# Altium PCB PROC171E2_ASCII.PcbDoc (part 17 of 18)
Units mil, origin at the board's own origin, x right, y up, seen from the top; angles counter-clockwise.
Board outline 7700 x 2300 mil, 6 copper layers (Top Layer, GND 1, SIG 1, SIG 2, GND 2, Bottom Layer), stack 61.062 mil thick; 938 components, 688 nets, 11933 pads, 1723 vias.
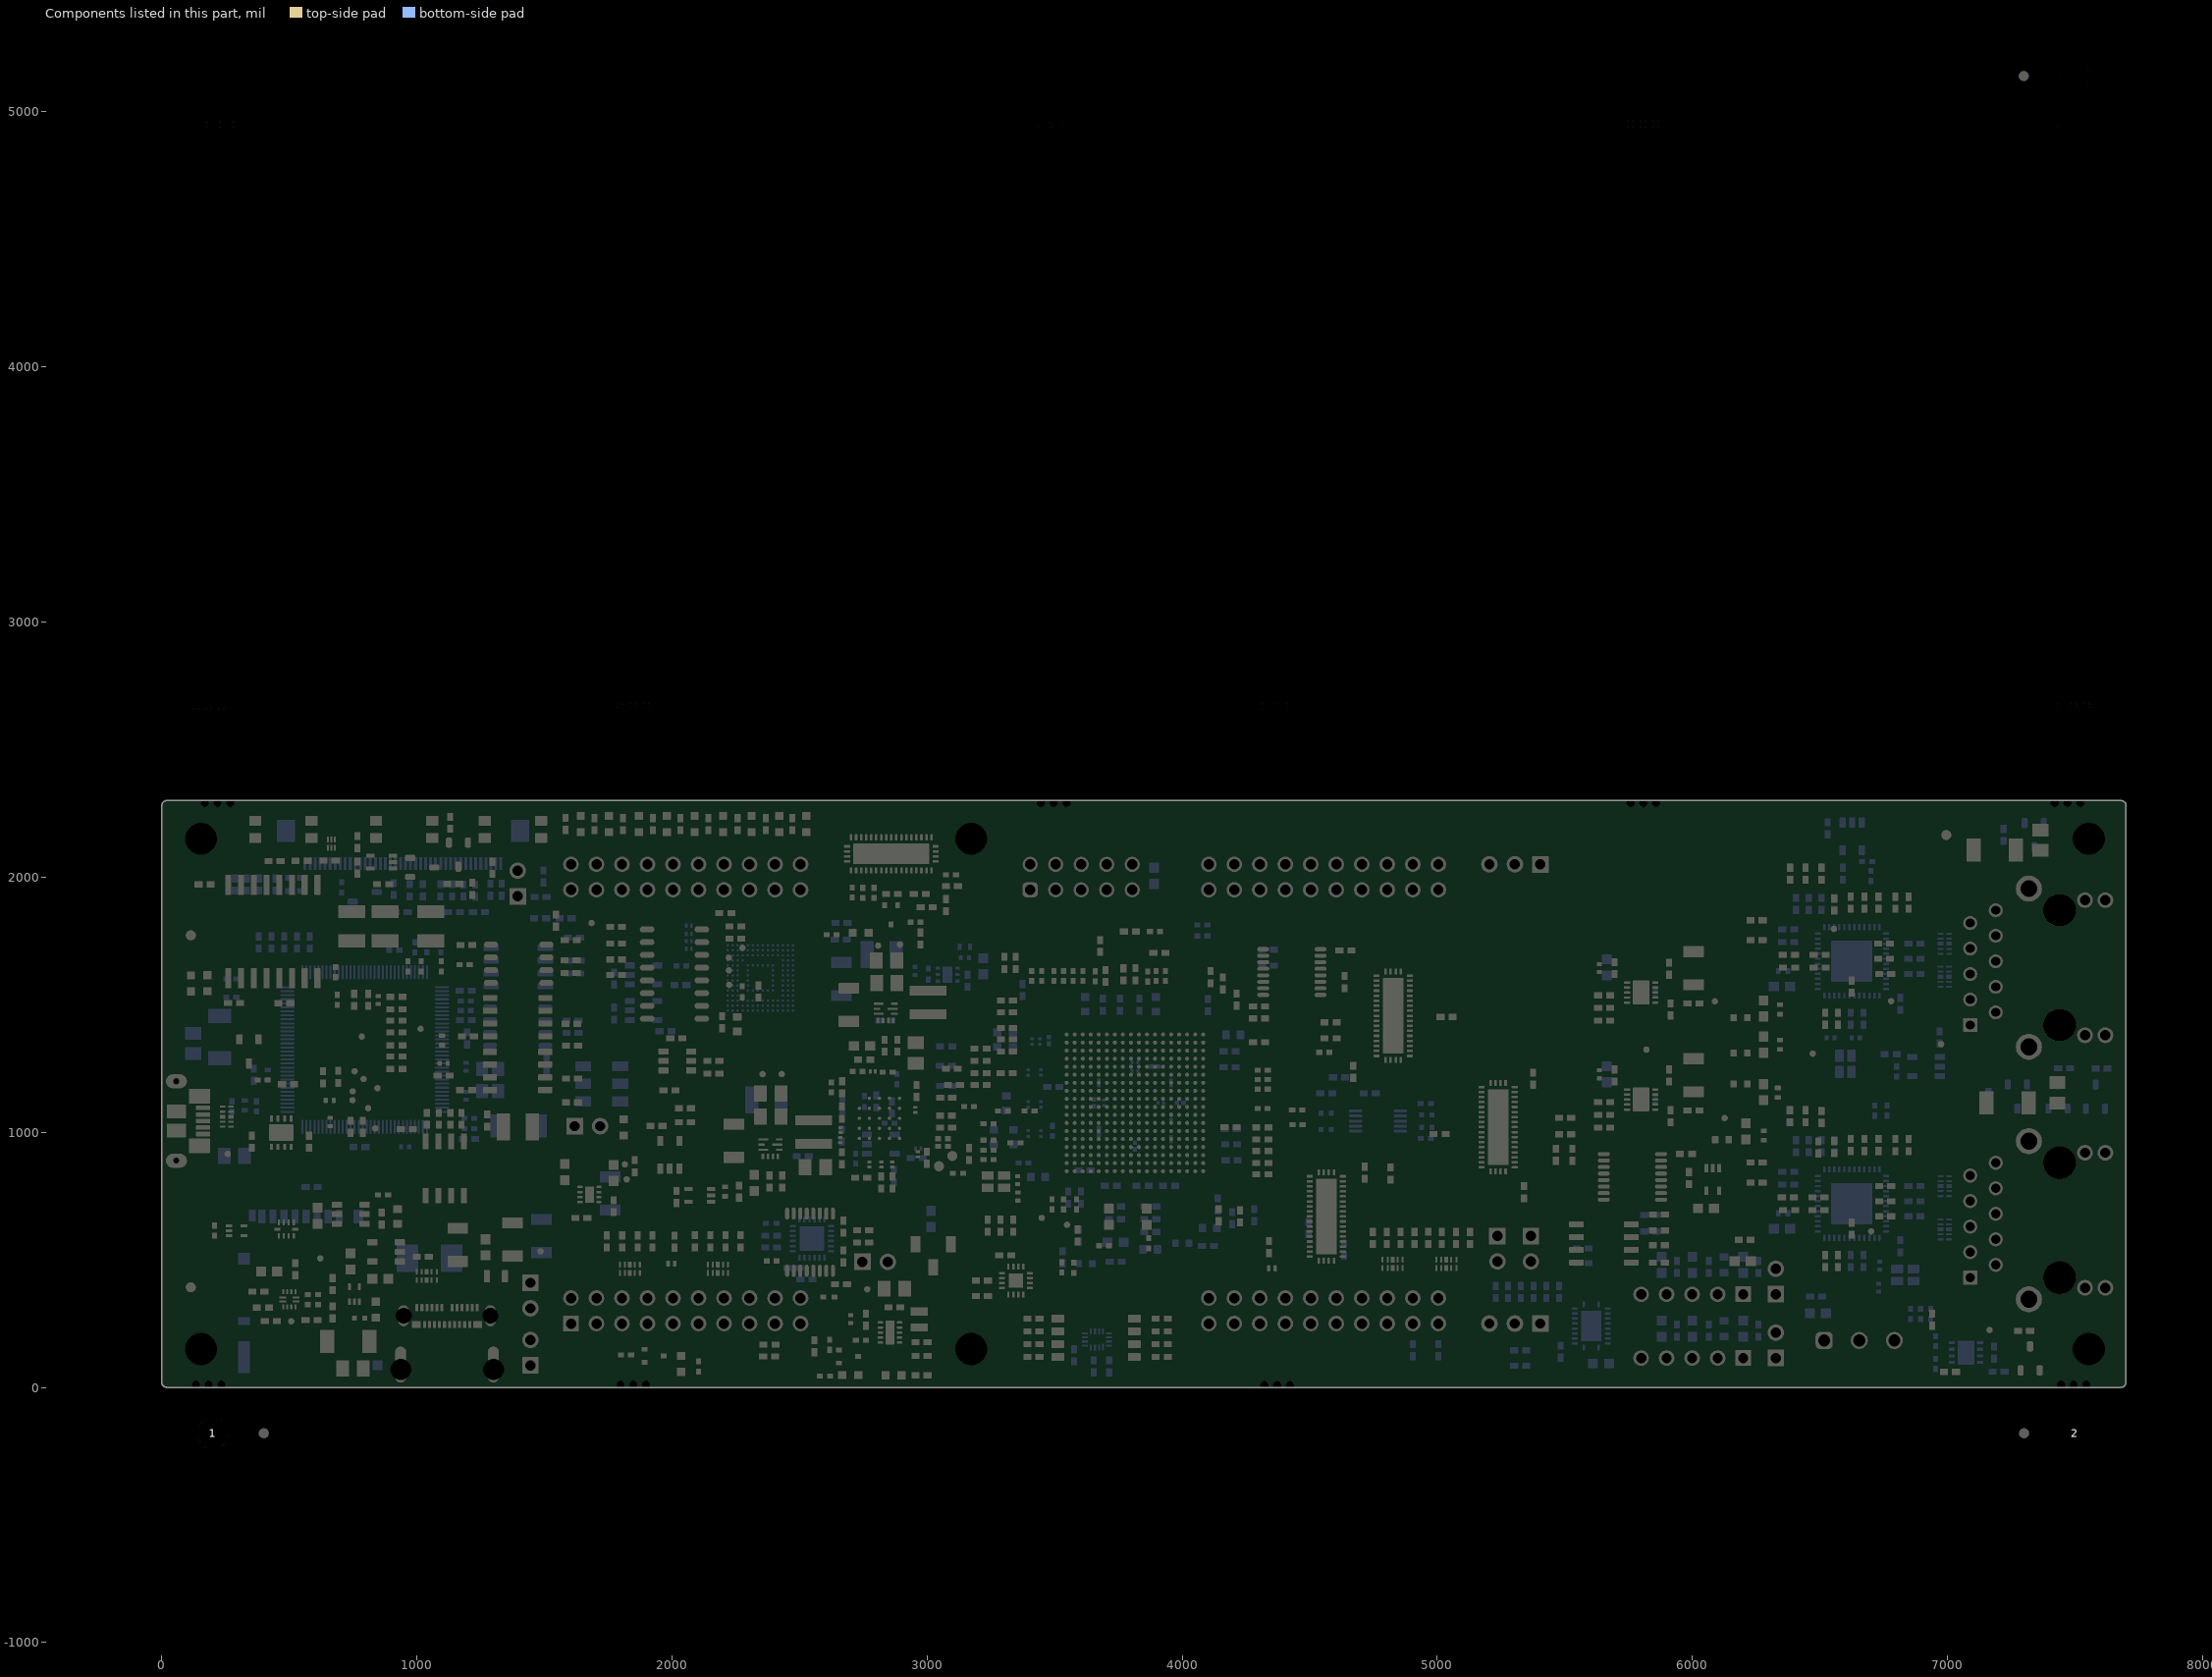
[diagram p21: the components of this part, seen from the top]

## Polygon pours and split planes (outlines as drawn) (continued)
VSYS_5V0 on Bottom Layer "Bottom Layer-VSYS_5V0 3" (solid, pour order 60): 2600.95,1572.62 2600.95,1544.48 2599.73,1543.26 2599.73,1507.06 2599.73,1343.69 2705.33,1343.69 2705.33,1361.19 2731.11,1361.19 2731.11,1458.15 2717.03,1458.15 2717.03,1572.62 2641.67,1572.62
GND on Bottom Layer "BOTTOM_LAYER_GND_P274" (solid, pour order 274): 2979.63,1538.35 3011.13,1538.35 3025.2,1552.42 3025.2,1571.85 3016.51,1580.54 3016.51,1612.03 2992.89,1612.03 2980.42,1624.51 2929.81,1624.51 2919.09,1613.79 2919.09,1536.37 2919.19,1536.27 2977.55,1536.27
GND on Bottom Layer "Bottom Layer-GND 10" (solid, pour order 251): 3217.83,1455 3217.83,1375 3319.11,1375 3335.71,1358.4 3534.15,1358.4 3553.51,1377.76 3553.51,1419.82 3518.33,1455
GND on Bottom Layer "Bottom Layer-GND 12" (solid, pour order 247): 3387.03,989 3368.89,970.85 3194.87,970.85 3185.85,961.83 3185.85,881.77 3248.25,819.37 3358.92,819.37 3375.74,802.54 3417.54,802.54 3427.57,812.57 3427.57,897.88 3468.86,939.16 3468.86,989
VDDS_AM263P_LDO_1V8 on Bottom Layer "Bottom Layer-VDDS_AM263_LDO_1V8" (solid, pour order 174): 29 vertices, not listed, extent 3446.81,751.21 4069.75,1493.61
GND on Bottom Layer "Bottom Layer-GND 7" (solid, pour order 146): 3865,722.41 3865,480.28 3745,480.28 3745,722.41
VSYS_3V3 on Bottom Layer "Bottom Layer-VSYS_3V3 1" (solid, pour order 142): 4100,680 4100,530.76 4015,530.76 4015,680
VDDA_AM263P_3V3 on Bottom Layer "Bottom Layer-VDDA_AM263_3V3" (solid, pour order 140): 18 vertices, not listed, extent 3693.61,515 4065,1056.95
GND on Bottom Layer "Bottom Layer-GND 1" (solid, pour order 94): 3230,1135 3322.46,1135 3482.32,1135 3482.32,1225 3230,1225
VDD_AM263P_1V2 on Bottom Layer "Bottom Layer-VDD_AM263_1V2" (solid, pour order 92): 3307.05,1115 3318.05,1104 3465.57,1104 3465.57,1000.24 3375.88,1000.24 3365.88,990 3230,990 3230,1115
VDD_AM263P_1V2 on Bottom Layer "Bottom Layer-VDD_AM263_1V2 1" (solid, pour order 90): 3219.58,1350 3219.58,1240 3496.91,1240 3496.91,1350
VSYS_3V3 on Bottom Layer "Bottom Layer-VSYS_3V3" (solid, pour order 58): 2851.67,1749.7 3050.16,1749.7 3050.16,1638.26 3049.59,1637.69 3029.26,1637.69 3019.36,1627.78 2992.89,1627.78 2980.42,1640.25 2857.77,1640.25 2851.67,1646.35
SHIELD4 on Bottom Layer "Bottom Layer-SHIELD4" (solid, pour order 116): 15,850 170,850 170,1163.44 275.25,1268.68 275.25,1333.26 15,1333.26
GND on Bottom Layer "BOTTOM_LAYER_GND_P272" (solid, pour order 272): 25 vertices, not listed, extent 1422.03,608.28 1810.59,859.03
GND on Bottom Layer "Bottom Layer-GND 9" (solid, pour order 180): 6654.01,1190.62 6695,1231.61 6695,1340.89 6723.27,1369.16 6723.27,1436.02 6650,1436.02 6650,1508.25 6545,1508.25 6545,1471.48 6545,1468.62 6545,1396.17 6473.24,1396.17 6473.24,1190.62
GND on Bottom Layer "Bottom Layer-GND 4" (solid, pour order 56): 2791.67,1750.06 2791.67,1791.87 2774.61,1808.93 2723.42,1808.93 2714.89,1817.46 2714.89,1832.05 2672.82,1832.05 2669.82,1829.05 2669.82,1732.84 2668.41,1731.43 2606.23,1731.43 2596.67,1721.87 2596.67,1632.62 2791.67,1632.62
GND on Bottom Layer "Bottom Layer-GND 5" (solid, pour order 46): 2189.18,1246.57 2189.18,1000 2340,1000 2340,1246.57
VSYS_5V0 on Bottom Layer "Bottom Layer-VSYS_5V0 4" (solid, pour order 42): 2175,940 2175,805 2315,805 2315,940
VSYS_5V0 on Bottom Layer "Bottom Layer-VSYS_5V0" (solid, pour order 30): 1703.99,724.88 1703.99,675.89 1897.88,675.89 1897.88,787.67 1825,787.67 1825,724.88
SHIELD2 on Bottom Layer "Top Layer-SHIELD2" (solid, remove dead copper, pour order 192): 7250,329.68 7306.81,272.87 7412.87,272.87 7505,365 7505,416.54 7528.25,439.79 7650,439.79 7650,853.43 7535,853.43 7470,918.43 7470,1140 7250,1140
SHIELD3 on Bottom Layer "Top Layer-SHIELD3" (solid, remove dead copper, pour order 190): 7233.03,2007 7233.03,1940.28 7250,1923.31 7250,1277.87 7442.87,1277.87 7505,1340 7505,1406.54 7528.25,1429.79 7650,1429.79 7650,1843.43 7535,1843.43 7470,1908.43 7470,2007
NetC257_1 on Bottom Layer "BOTTOM_LAYER_NETC257_1_P265" (solid, pour order 265): 3616.47,912.31 3595.39,933.39 3566.83,961.95 3566.83,982.15 3590,1005.32 3641.14,1005.32 3647.25,999.21 3647.25,983.47 3678.96,951.75 3678.96,853.04 3661.4,835.48 3628.7,835.48 3616.47,847.7
GND on Bottom Layer "BOTTOM_LAYER_GND_P279" (solid, pour order 279): 1005.14,451.45 888.52,451.45 842.94,497.03 842.94,575.34 882.6,615 990.81,615 1005.14,600.67 1005.14,559.44
VBUS_TYPEC_5V0 on Bottom Layer "Bottom Layer-VBUS_TYPEC_5V0" (solid, pour order 4): 1054.51,330 1043.53,340.98 1043.53,381.59 1093.26,431.32 1093.26,464.11 1093.26,558.55 1095.5,560.79 1300,560.79 1300,330
GND on Bottom Layer "BOTTOM_LAYER_GND_P273" (solid, pour order 273): 23 vertices, not listed, extent 3060.58,1507.06 3170.99,1739.09
VDD_AM263P_1V2 on Bottom Layer "Bottom Layer-VDD_AM263_1V2 3" (solid, pour order 44): 2400,1208.74 2420.1,1228.84 2585.45,1228.84 2604.32,1209.96 2602.9,1166.54 2602.9,1099.73 2558.17,1055 2400,1055
VSYS_TA_3V3 on Bottom Layer "Bottom Layer-VSYS_TA_3V3" (solid, pour order 134): 530,2115.46 530,1913.95 609.37,1913.95 609.37,2115.46
GND on Bottom Layer "Bottom Layer-GND 11" (solid, pour order 229): 26 vertices, not listed, extent 3649.62,1070.33 3987.86,1220.93
VPP_AM263P_1V7 on Bottom Layer "BOTTOM_LAYER_VPP_AM263P_1V7_P268" (solid, remove dead copper, pour order 268): 3160.8,1739.09 3238.74,1739.09 3238.74,1662.62 3159.06,1662.62 3156.17,1659.74 3156.17,1692.48 3160.8,1697.11
GND_XDS on Bottom Layer "Bottom Layer-GND_XDS" (solid, pour order 118): 75,1363.74 279.76,1363.74 279.76,1508.25 75,1508.25
GND on Bottom Layer "Bottom Layer-GND 2" (solid, pour order 80): 5565,1659.19 5755,1659.19 5755,1799.19 5565,1799.19
SHIELD1 on Bottom Layer "Top Layer-SHIELD1" (solid, pour order 241): 970,333.27 970,173.86 1268.3,173.86 1268.3,333.27 1335,333.27 1335,14.25 760,14.25 760,94.25 779.9,114.15 779.9,213.5 881.02,213.5 881.02,333.27
GND on Bottom Layer "Bottom Layer-GND 6" (solid, pour order 110): 595,40 875.12,40 875.12,190 595,190
VSYS_5V0 on Bottom Layer "Bottom Layer-VSYS_5V0 1" (solid, pour order 82): 5579.67,1634.19 5579.67,1508.91 5695,1508.91 5695,1634.19
VBUS_XDS_5V0 on Bottom Layer "Bottom Layer-VBUS_USBMICRO_5V0" (solid, pour order 152): 275,845.04 195,845.04 195,1015 275,1015
GND on Bottom Layer "Bottom Layer-GND 3" (solid, pour order 72): 5565,1240 5755,1240 5755,1318.86 5565,1318.86
VSYS_5V0 on Bottom Layer "Bottom Layer-VSYS_5V0 2" (solid, pour order 70): 5485,1215 5485,1142.56 5695,1142.56 5695,1215
VSYS_3V3 on SIG 2 "SIG 2-VSYS_3V3" (solid, remove dead copper, pour order 196): 94 vertices, not listed, extent 125,40 7665,2240
VSYS_5V0 on SIG 2 "SIG 1-VSYS_5V0" (solid, remove dead copper, pour order 170): 51 vertices, not listed, extent 1795,40 7230,1660
VSYS_3V3_BP on SIG 2 "NONET_L-01_P-001" (solid, remove dead copper, pour order 296): 17 vertices, not listed, extent 1516.48,0 4156.27,423.8
VSD_3V3 on SIG 2 "SIG 2-VSD_3V3" (solid, pour order 160): 220,632 255.85,667.85 255.85,746.73 260.35,751.23 263.56,751.21 498.97,751.21 498.97,820 631.97,820 631.97,567.83 220,567.83
VDD_AM263P_1V2 on SIG 2 "SIG 1-VDD_AM263_1V2" (solid, pour order 168): 28 vertices, not listed, extent 2463.31,783.77 4050,1334.96
VDD_ETH2_1V1_FILT on SIG 2 "SIG 2-VDD_ETH2_1V1_FILT" (solid, pour order 12): 18 vertices, not listed, extent 6259.18,1433.78 6846.59,1934.26
VDD_XDS3V3 on SIG 2 "SIG 1-VDD_XDS3V3" (solid, pour order 194): 160,840 160,1830 624.78,1830 624.78,1776.08 1364.62,1776.08 1364.62,905 420,905 420,840
VDD_ETH1_1V1_FILT on SIG 2 "SIG 2-VDD_ETH1_1V1_FILT" (solid, pour order 84): 17 vertices, not listed, extent 6338.15,689.1 6955,1339.91
VDDS_AM263P_LDO_1V8 on SIG 2 "SIG 2-VDDS_AM263_LDO_1V8 1" (solid, pour order 16): 3710,1305.1 3710,1416.01 3713.99,1420 3713.99,1460.97 3705,1469.95 3672.32,1469.95 3657.37,1455 3657.37,1415.8 3630.74,1389.17 3630.74,1315.74 3651.48,1295 3699.9,1295
SHIELD2 on SIG 2 "Top Layer-SHIELD2" (solid, pour order 211): 7250,329.68 7306.81,272.87 7412.87,272.87 7505,365 7505,416.54 7528.25,439.79 7650,439.79 7650,853.43 7535,853.43 7470,918.43 7470,1140 7250,1140
SHIELD3 on SIG 2 "Top Layer-SHIELD3" (solid, pour order 209): 7233.03,2130 7233.03,1940.28 7250,1923.31 7250,1277.87 7265,1262.87 7427.87,1262.87 7505,1340 7505,1406.54 7528.25,1429.79 7650,1429.79 7650,1843.43 7535,1843.43 7470,1908.43 7470,2130
VDDS_AM263P_LDO_1V8 on SIG 2 "SIG 2-VDDS_AM263_LDO_1V8" (solid, pour order 14): 4144.81,1277.63 4076.04,1277.63 4061.86,1291.81 3993.63,1291.81 3993.63,1253.31 4057.7,1253.31 4091.01,1220 4140.09,1220 4154.85,1234.76 4154.85,1267.72 4143.94,1278.63
GND on GND 1 "GND 1-GND" (solid, remove dead copper, pour order 200): 68 vertices, not listed, extent 85,20 7670,2275.01
GND_XDS on GND 1 "SIG 1-VDD_XDS3V3" (solid, pour order 150): 280.17,1285.5 180,1185.32 180,1159.28 180,840 420,840 420,905 1364.62,905 1364.62,1776.08 624.78,1776.08 624.78,1830 60,1830 60,1365 280.17,1365
SHIELD1 on GND 1 "Top Layer-SHIELD1" (solid, pour order 148): 970,333.27 970,173.86 1268.3,173.86 1268.3,333.27 1335,333.27 1335,14.25 760,14.25 760,94.25 779.9,114.15 779.9,213.5 881.02,213.5 881.02,333.27
SHIELD3 on GND 1 "Top Layer-SHIELD3" (solid, pour order 235): 7233.03,2130 7210,2106.97 7210,1963.31 7250,1923.31 7250,1277.87 7265,1262.87 7427.87,1262.87 7505,1340 7505,1406.54 7528.25,1429.79 7650,1429.79 7650,1843.43 7535,1843.43 7470,1908.43 7470,2130
SHIELD2 on GND 1 "Top Layer-SHIELD2" (solid, pour order 203): 7250,329.68 7306.81,272.87 7412.87,272.87 7505,365 7505,416.54 7528.25,439.79 7650,439.79 7650,853.43 7535,853.43 7470,918.43 7470,1140 7250,1140
SHIELD4 on GND 1 "Bottom Layer-SHIELD4" (solid, pour order 158): 15,840 170,840 170,1189.07 270,1289.07 270,1333.26 15,1333.26
GND on SIG 1 "NONET_L-01_P-001" (solid, remove dead copper, pour order 297): 7681.99,2300 7700,2281.99 7700,18.01 7681.99,0 18.01,0 0,18.01 0,2280 20,2300
VUSB_5V0 on SIG 1 "NONET_L-01_P-001" (solid, remove dead copper, pour order 293): 32 vertices, not listed, extent 2623.53,9 5540,640.9
GND_XDS on SIG 1 "SIG 1-VDD_XDS3V3" (solid, remove dead copper, pour order 289): 181.42,840 181.42,1186.74 280.17,1285.5 280.17,1362.13 62.87,1362.13 60,1365 60,1830 524.78,1830 524.78,1776.08 1364.62,1776.08 1364.62,905 420,905 420,840
SHIELD4 on SIG 1 "Bottom Layer-SHIELD4" (solid, pour order 205): 25.49,840 159.15,840 159.15,1194.39 259.71,1294.95 259.71,1333.26 25.49,1333.26
VDDA_AM263P_1V8_LDO on SIG 1 "SIG 1-VDDA_AM263_1V8_LDO" (solid, pour order 221): 29 vertices, not listed, extent 3591.01,641.74 4142.51,1049.87
SHIELD1 on SIG 1 "Top Layer-SHIELD1" (solid, pour order 261): 970,333.27 970,173.86 1268.3,173.86 1268.3,333.27 1335,333.27 1335,14.25 760,14.25 760,94.25 779.9,114.15 779.9,213.5 881.02,213.5 881.02,333.27
VDDS_AM263P_LDO_1V8 on SIG 1 "SIG 1-VDDS_AM263_LDO_1V8 2" (solid, pour order 207): 3981.72,965.48 4160,965.48 4160,1020 4147.43,1032.57 3981.72,1032.57
VDDS_AM263P_LDO_1V8 on SIG 1 "SIG 1-VDDS_AM263_LDO_1V8 1" (solid, pour order 237): 3674.62,1460 3664.99,1450.37 3664.99,1309.77 3681.25,1293.51 3709.82,1293.51 3725,1308.69 3725,1450 3715,1460
VDDA18_AM263P_OSC_PLL on SIG 1 "SIG 1-VDDA18_AM263_OSC_PLL" (solid, remove dead copper, pour order 285): 22 vertices, not listed, extent 3470,591.26 3648.81,934.4
VDDS_AM263P_LDO_1V8 on SIG 1 "SIG 1-VDDS_AM263_LDO_1V8" (solid, pour order 227): 3573.07,908.07 3497,832 3497,780.82 3507.82,770 3576.79,770 3595,788.21 3595,870.25 3609.75,885 3609.75,898.64 3600.33,908.07
VSYS_3V3 on SIG 1 "SIG 1-VSYS_3V3" (solid, pour order 172): 3761.09,1315 3740.37,1315 3734.14,1308.77 3734.14,1280.46 3634.97,1280.46 3635.03,1198.85 3630.01,1193.83 3614.32,1193.83 3613.09,1192.6 3613.09,1128.91 3634,1108 3804.17,1108 3804.17,1287.1 3775.08,1316.2 3761.09,1316.2
VDDS_AM263P_LDO_1V8 on SIG 1 "SIG 1-VDDS_AM263_LDO_1V8 3" (solid, pour order 225): 3987.37,1248.64 3995,1241.01 4139.08,1241.01 4145.95,1247.88 4145.95,1264.05 4135,1275 4089.77,1275 4081.83,1267.05 4032.51,1267.05 4010.16,1289.4 3991.97,1289.4 3987.37,1284.8
SHIELD2 on SIG 1 "Top Layer-SHIELD2" (solid, pour order 219): 7250,329.68 7306.81,272.87 7412.87,272.87 7505,365 7505,416.54 7528.25,439.79 7650,439.79 7650,853.43 7535,853.43 7470,918.43 7470,1140 7250,1140
SHIELD3 on SIG 1 "Top Layer-SHIELD3" (solid, pour order 217): 7233.03,2130 7210,2106.97 7210,1963.31 7250,1923.31 7250,1277.87 7442.87,1277.87 7505,1340 7505,1406.54 7528.25,1429.79 7650,1429.79 7650,1843.43 7535,1843.43 7470,1908.43 7470,2130
GND on GND 2 "GND 1-GND" (solid, remove dead copper, pour order 186): 65 vertices, not listed, extent 85,20 7660,2275
GND_XDS on GND 2 "SIG 1-VDD_XDS3V3" (solid, pour order 188): 280.17,1285.5 180,1185.32 180,1159.28 180,840 420,840 420,905 1364.62,905 1364.62,1776.08 624.78,1776.08 624.78,1830 60,1830 60,1365 280.17,1365
SHIELD1 on GND 2 "Top Layer-SHIELD1" (solid, pour order 184): 970,333.27 970,173.86 1268.3,173.86 1268.3,333.27 1335,333.27 1335,14.25 760,14.25 760,94.25 779.9,114.15 779.9,213.5 881.02,213.5 881.02,333.27
SHIELD2 on GND 2 "Top Layer-SHIELD2" (solid, pour order 239): 7250,329.68 7306.81,272.87 7412.87,272.87 7505,365 7505,416.54 7528.25,439.79 7650,439.79 7650,853.43 7535,853.43 7470,918.43 7470,1140 7250,1140
SHIELD3 on GND 2 "Top Layer-SHIELD3" (solid, pour order 215): 7233.03,2006.22 7233.03,1940.28 7250,1923.31 7250,1277.87 7265,1262.87 7427.87,1262.87 7505,1340 7505,1406.54 7528.25,1429.79 7650,1429.79 7650,1843.43 7509.96,1843.43 7347.16,2006.22
SHIELD4 on GND 2 "Bottom Layer-SHIELD4" (solid, pour order 213): 15,850 170,850 170,1189.07 270,1289.07 270,1333.26 15,1333.26

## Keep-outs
Keep-Out Layer:
  lines w20: -145,800.57 460,800.57 460,865 1400,865 1400,1809.3 658.26,1809.3 658.26,1875 -125,1875
  text ".Layer_Name" at 577,-858.49 h60

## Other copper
Top Layer:
  text ".Layer_Name" at 577,-858.49 h60
SIG 1:
  text ".Layer_Name" at 633.55,-861.02 h60
SIG 2:
  text ".Layer_Name" at 681.73,-882.02 h60
GND 1:
  text ".Layer_Name" at 665,-871.02 h60
GND 2:
  text ".Layer_Name" at 781.72,-861.02 h60
Bottom Layer:
  text ".Layer_Name" at 577,-858.49 h60

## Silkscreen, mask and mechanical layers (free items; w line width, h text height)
Top Overlay:
  lines w4: 2556.81,1860.14 2577.74,1907.93
  lines w5: 931,2028 931,1993 931,1974 940,1965
  lines w6: 2485.19,1298.9 2672.64,1298.9 ; 2600,1453.47 2636.66,1453.47 2636.66,1298.9 ; 2688.99,1258.76 2688.99,1298.9 2672.64,1298.9 ; 2706,1387.3 2672.64,1387.3 2672.64,1298.9 ; 1515.26,2156.74 1535.31,2136.69 1554.86,2156.24 1554.86,2275 1515.26,2275 1515.26,2156.74 ; 1563,459.18 1591.51,430.67 1623.5,462.66 1623.5,579 1563,579 1563,459.18 ; 1638.5,460.5 1638.5,586.5 1703.5,586.5 1703.5,462.5 1670,429 1638.5,460.5 ; 3385.35,1871.38 3419.92,1871.38 3420,1871.46 3430,1871.46 3407.72,1893.74 3385.35,1871.38 ; 4065,2144 4065,2270 4150,2270 4150,2146 4106.5,2102.5 4065,2144 ; 6180.35,34.92 6202.72,57.28 6225,35 6215,35 6214.92,34.92 6180.35,34.92 ; 6180.35,281.78 6202.72,304.14 6225,281.86 6215,281.86 6214.92,281.78 6180.35,281.78
  lines w10: 217.17,1928 231.92,1928 231.92,2017.75 544.26,2017.75 544.26,2025.46 543.88,2025.46 ; 875.74,1563.98 875.74,1603.51 1241.06,1603.51 1241.06,1461.43 983.47,1461.43 983.47,1303.2 978.27,1303.2 ; 1059.65,1145.26 1129.53,1145.26 1129.53,1114.92 ; 2798.79,1843.85 2802.41,1843.85 2802.41,1897.03 ; 2808.45,570 2841.89,570 2841.89,576.95
  text "RESETn" at 658,2252 h50
  text "SW2" at 233,2249 h30
  text "SW3" at 720.47,2214.24 h30
  text "PORZ" at 216,2203 h50
  text "SW4" at 1230,2179 h30 r90
  text "U34" at 645.44,2174.49 h30
  text "INT1" at 1193,2172 h50 r90
  text "GND" at 1546.78,2164.75 h25 r90
  text "GND" at 4129,2150 h40 r90
  text "FSI" at 3480,2146.38 h100
  text "SL#" at 6095,2140 h108.27
  text "3V3" at 5455.61,2120 h50 r90
  text "GND" at 5315,2112.06 h50 r90
  text "59" at 4187.19,2111.37 h25
  text "58" at 4285.98,2111.37 h25
  text "57" at 4389.77,2111.37 h25
  text "56" at 4487.53,2111.37 h25
  text "55" at 4596.53,2111.37 h25
  text "54" at 4691.69,2111.37 h25
  text "53" at 4786.86,2111.37 h25
  text "52" at 4881.15,2111.37 h25
  text "GND" at 5217.15,2110 h50 r90
  text "D14" at 1601.15,2097.81 h30
  text "D13" at 1720.33,2097.81 h30
  text "D12" at 1835.7,2097.81 h30
  text "D11" at 1948.01,2097.81 h30
  text "D10" at 2053.44,2097.81 h30
  text "D9" at 2171.1,2097.81 h30
  text "D8" at 2287.99,2097.81 h30
  text "D7" at 2400.35,2097.81 h30
  text "D4" at 2525.75,2097.81 h30
  text "Q2" at 1093,2064 h30 r90
  text "Q3" at 1200,2016 h30
  text "J12" at 5245.35,1944.87 h30
  text "J8" at 6933.56,1910 h30
  text "U33" at 978,1894 h30 r90
  text "39" at 1663.16,1884.15 h25
  text "38" at 1763.06,1884.15 h25
  text "37" at 1878.71,1884.15 h25
  text "36" at 1970.22,1884.15 h25
  text "35" at 2071.15,1884.15 h25
  text "34" at 2187.19,1884.15 h25
  text "33" at 2271.23,1884.15 h25
  text "32" at 2382.79,1884.15 h25
  text "73" at 4789.83,1884.01 h25
  text "79" at 4189.39,1883.47 h25
  text "78" at 4282.48,1882.53 h25
  text "75" at 4586.19,1883.47 h25
  text "76" at 4484.65,1879.72 h25
  text "77" at 4392.49,1878.79 h25
  text "72" at 4885.12,1878.82 h25
  text "74" at 4688.68,1876.89 h25
  text "J23" at 3588.88,1846.72 h30
  text "J1" at 1369.98,1835.38 h30
  text "U48" at 1984.11,1827.9 h30
  text "U25" at 1336.62,1773.69 h30
  text "Q10" at 2830,1762 h30
  text "DS1" at 2670,1707 h30
  text "ERROR" at 2607,1657 h30
  text "U31" at 5761.5,1650.88 h30
  text "L3" at 3001.87,1614.58 h30
  text "LP-AM263P" at 5128.09,1555.53 h75
  text "U26" at 1547.88,1489.07 h30
  text "U32" at 2784.03,1453.47 h30 r90
  text "'.PRJ_Number''.PCB_Rev'" at 5128.09,1435.72 h75
  text "U28" at 304.03,1398.06 h30
  text "ICSSM_MII0" at 6983.84,1395.24 h30 r90
  text "CPSW RGMII2/" at 6918.84,1391.97 h30 r90
  text "XDS110" at 40,1321.39 h50
  text "UART0" at 50,1271.09 h50
  text "U2" at 1874.58,1270.52 h30
  text "TP26" at 760.65,1267.76 h30 r90
  text "U30" at 5761.03,1226.23 h30
  text "U27" at 1247.27,1222.02 h30 r90
  text "U23" at 4791.84,1220.55 h30
  text "U1" at 3456.49,1211.65 h30
  text "J34" at 245.29,1137.61 h30 r90
  text "D2" at 1792.08,1107.78 h30
  text "L2" at 2518.73,1097.5 h30
  text "ADC_VREF" at 1704.17,1094.67 h30 r90
  text "U45" at 452.28,1092.49 h30
  text "J17" at 1751.08,1090 h30 r90
  text "U44" at 326.37,1031.43 h30 r90
  text "U7" at 2976.6,999.16 h30 r90
  text "U29" at 2330.07,930.38 h25 r90
  text "U5" at 2073.66,904.05 h30
  text "J7" at 6938.53,860 h30
  text "U19" at 1642.67,828.66 h30
  text "U8" at 712.47,762.13 h30
  text "Y1" at 3236.81,717.66 h30
  text "U11" at 452.28,685 h30
  text "3V3" at 5205,675 h50
  text "5V0" at 5347.64,663.97 h50
  text "U6" at 2087.02,662 h30
  text "J16" at 6287.06,533.25 h30
  text "U3" at 3373.45,502.13 h30
  text "J10" at 1415,474 h30
  text "GND" at 1692.5,466.5 h40 r90
  text "U14" at 4670.47,462.28 h30
  text "U13" at 2251.21,449.64 h30
  text "EQEP2" at 5960,443.25 h50
  text "U12" at 1762.07,426.33 h30 r90
  text "U15" at 4996.51,411.21 h30
  text "J13" at 5191.02,394.66 h30
  text "22" at 1690.01,393.63 h25
  text "23" at 1780.97,393.63 h25
  text "24" at 1895.37,393.63 h25
  text "25" at 1999.84,393.63 h25
  text "26" at 2085.17,393.63 h25
  text "27" at 2176.47,393.63 h25
  text "28" at 2285.16,393.63 h25
  text "29" at 2387.84,393.63 h25
  text "62" at 4212.61,394.19 h25
  text "63" at 4297.08,394.19 h25
  text "64" at 4393.34,394.19 h25
  text "65" at 4494.82,394.19 h25
  text "66" at 4596.31,394.19 h25
  text "67" at 4693.88,394.19 h25
  text "68" at 4778.63,394.19 h25
  text "69" at 4905.77,394.19 h25
  text "U18" at 433.75,392.88 h25
  text "J14" at 5326.51,389.83 h30
  text "ICSSM_MII1" at 7000,363.27 h30 r90
  text "CPSW RGMII1/" at 6935,360 h30 r90
  text "J33" at 6530,353 h30
  text "SW1" at 3611.51,344.83 h30
  text "MCAN0" at 6685,344.96 h30
  text "PWR IN" at 1024.37,336.56 h80
  text "J11" at 5249.61,325.69 h30
  text "J25" at 5945.82,273.88 h30
  text "DAC_VREF" at 3035.51,264.86 h50
  text "U21" at 730.46,241.77 h30 r90
  text "J15" at 6182.73,215 h30
  text "EQEP0" at 5930,210 h50
  text "49" at 4924.23,184.59 h25
  text "8" at 2281.11,180.24 h25
  text "6" at 2060.99,179.22 h25
  text "9" at 2439.07,179.22 h25
  text "2" at 1698.79,177.88 h25
  text "7" at 2201.1,177.51 h25
  text "3" at 1796.34,177.23 h25
  text "4" at 1863.37,176.75 h25
  text "5" at 1976.82,177.15 h25
  text "46" at 4586.56,172.36 h25
  text "48" at 4774.61,170.67 h25
  text "44" at 4380.24,168.96 h25
  text "42" at 4192.29,168.31 h25
  text "43" at 4289.84,167.66 h25
  text "45" at 4470.32,167.58 h25
  text "47" at 4694.6,167.94 h25
  text "PWR BAD" at 903.93,167.49 h25 r90
  text "J18" at 2162.47,130.81 h30
  text "D5" at 2113.99,125.01 h30 r90
  text "J24" at 5645,115 h30
  text "U36" at 2820.82,110.9 h30
  text "5V0" at 5428.52,110 h50 r90
  text "CANA_N" at 6430,110 h30 r90
  text "J9" at 1375.17,109.01 h30 r90
  text "GND" at 5222.77,93.16 h50 r90
  text "D6" at 2758.45,91.58 h30
  text "GND" at 5324.39,90 h50 r90
  text "Q5" at 7160,80 h30
  text "uSD" at 390.11,60.39 h108.27
  text "J5" at 847.95,55.73 h30
  text "HIGH" at 3364,43.5 h30
  text "LOW" at 3885,43.5 h30
  text "CANA_P" at 6910,39.9 h30 r90
  text "BOOTMODE" at 3543,17.5 h30
  text ".Layer_Name" at 577,-858.49 h60
Bottom Overlay:
  drawing of 4382 lines, arcs and shapes, not listed
  text "J6" at 387,2198 h30
  text "15" at 2120,2109 h25
  text "20" at 1669,2108 h25
  text "19" at 1730,2108 h25
  text "18" at 1812,2108 h25
  text "17" at 1916,2108 h25
  text "16" at 2018,2108 h25
  text "14" at 2221,2108 h25
  text "13" at 2323,2108 h25
  text "12" at 2422,2108 h25
  text "11" at 2540,2108 h25
  text "Q7" at 7336.65,2043.21 h30
  text "Q1" at 744.77,1843.92 h30
  text "www.ti.com/launchpad" at 5569,1824.95 h30
  text "R182" at 572.49,1810.42 h25 r270
  text "U40" at 7031.35,1810.13 h30
  text "TEST AUTOMATION HEADER" at 1417,1799 h30
  text "U41" at 7016.92,1512.28 h30
  text "U37" at 6465,1486.82 h30
  text "U24" at 430.32,1411.43 h30
  text "U9" at 1904.69,1373.8 h30
  text "LP-AM263P" at 5388.55,1334.95 h30
  text "VREF Select" at 2002,1320 h30
  text "Development Kit" at 5470.55,1263.95 h30
  text "4" at 1596.57,1247.62 h30
  text "1" at 1864.39,1245 h30
  text "Y3" at 1364.03,1172.91 h30 r270
  text "6" at 1602.07,1104.9 h30
  text "3" at 1875.39,1104.9 h30
  text "Q4" at 7265,1027.71 h30
  text "Q8" at 7467.49,1021.98 h30
  text "Q9" at 7595,1011.5 h30
  text "U17" at 4799.98,934.56 h30
  text "C234" at 1452.28,919.6 h30
  text "U38" at 7017.5,871.84 h30
  text "J2" at 766.19,730.8 h30
  text "U22" at 6440.74,639.7 h30 r270
  text "D1" at 1091.87,602.79 h30
  text "uSD" at 245,583.95 h108.27
  text "GND" at 4220,535.5 h36 r90
  text "U39" at 7010,510.96 h30
  text "Y2" at 6960,429.59 h30
  text "U43" at 5636.86,375 h30
  text "U4" at 3700.76,258.74 h30
  text "U42" at 7105,230 h30
  text "Q6" at 7420,196.5 h30
  text ".Layer_Name" at 577,-858.49 h60
Top Paste:
  text ".Layer_Name" at 577,-858.49 h60
Bottom Paste:
  text ".Layer_Name" at 577,-858.49 h60
Top Solder:
  text ".Layer_Name" at 577,-858.49 h60
  text ".Layer_Name" at 577,-858.49 h60
Bottom Solder:
  text ".Layer_Name" at 577,-858.49 h60
Drill Guide:
  text ".Layer_Name" at 577,-858.49 h60
M1 Board Outline:
  drawing of 179 lines, arcs and shapes, not listed
  text ".Layer_Name" at 582,-785 h40
M2 Board Dimensions:
  rectangle: 0,-275 125,-150
  rectangle: 125,-400 500,-275
  lines w7: 0,-275 1000,-275 ; 125,-400 125,-150 ; 250,-400 250,-150 ; 500,-400 500,-150 ; 750,-400 750,-150 ; 0,-400 1000,-400 1000,-150 0,-150 0,-400
  text ".Layer_Name" at 582,-893 h60
M3 3D STEP Top:
  text ".Layer_Name" at 577,-858.49 h60
M4 3D STEP Bottom:
  text ".Layer_Name" at 577,-858.49 h60
M5 Assembly Top:
  lines w4: 2800.78,1252.14 2809.2,1257.84
  lines w10: -292,-930.17 6308,-930.17 ; -292,-726.83 6310,-726.83 ; -292,-523.5 -292,-1133.5 3713,-1133.5 6310,-1133.5 6310,-523.5 -291.5,-523.5 -291.5,-1133.5 1284,-1133.5 ; 2173,-1133.5 2173,-523.5 ; 3440,-726.83 3440,-523.5 ; 4280,-726.83 4280,-523.5 ; 4902,-1140 4902,-937.17
  text "COMPONENTS MARKED 'DNP' SHOULD NOT BE POPULATED." at 1153.5,-377.5 h60
  text "ASSEMBLY VARIANT:" at 1153,-493 h60
  text ".VariantName" at 2189,-493 h60
  text "PCB VIEWED FROM TOP SIDE" at -228.5,-655.67 h60
  text "BOARD #:" at 2248,-655.67 h60
  text ".PRJ_Number" at 2793.5,-655.67 h60
  text "REV:" at 3638,-655.67 h60
  text ".PCB_Rev" at 3929.5,-655.67 h60
  text "SVN REV:" at 4476,-655.67 h60
  text ".VersionControl_RevNumber" at 4982,-655.67 h60
  text ".Layer_Name" at 588.78,-851.03 h60
  text "TID #:" at 2248,-859 h60
  text ".TID" at 2793.5,-859 h60
  text "PLOT NAME =" at -228.5,-1064.34 h60
  text ".plot_File_Name" at 577,-1064.34 h60
  text "GENERATED    :" at 2250,-1064.34 h60
  text ".Print_Date" at 3119.5,-1064.34 h60
  text ".Print_Time" at 3848.5,-1064.34 h60
  text "TEXAS INSTRUMENTS" at 5113,-1064.34 h60
M6 Assembly Bottom:
  lines w10: -292.5,-727.33 6309.5,-727.33 ; -290.5,-930.67 6309.5,-930.67 ; 1115.5,-1140.5 1115.5,-937.67 ; 1737.5,-727.33 1737.5,-524 ; 2577.5,-727.33 2577.5,-524 ; 3844.5,-1134 3844.5,-524 ; 4733.5,-1134 6309,-1134 6309,-524 -292.5,-524 -292.5,-1134 2304.5,-1134 6309.5,-1134 6309.5,-524
  text "COMPONENTS MARKED 'DNP' SHOULD NOT BE POPULATED." at 6096,-380 h60
  text ".VariantName" at 5052,-496 h60
  text "ASSEMBLY VARIANT:" at 6091,-496 h60
  text ".VersionControl_RevNumber" at 1035.5,-656.17 h60
  text "SVN REV:" at 1541.5,-656.17 h60
  text ".PCB_Rev" at 2088,-656.17 h60
  text "REV:" at 2379.5,-656.17 h60
  text ".PRJ_Number" at 3224,-656.17 h60
  text "BOARD #:" at 3769.5,-656.17 h60
  text "PCB VIEWED FROM BOTTOM SIDE" at 6246,-656.17 h60
  text ".Layer_Name" at 5742.29,-844.14 h60
  text ".TID" at 3224,-859.5 h60
  text "TID #:" at 3769.5,-859.5 h60
  text "TEXAS INSTRUMENTS" at 904.5,-1064.84 h60
  text ".Print_Time" at 2169,-1064.84 h60
  text ".Print_Date" at 2898,-1064.84 h60
  text "GENERATED    :" at 3767.5,-1064.84 h60
  text ".plot_File_Name" at 5440.5,-1064.84 h60
  text "PLOT NAME =" at 6246,-1064.84 h60
M9 Title Sheet:
  lines w10: -491.5,1041.5 -291.5,1041.5 ; -491.5,3416.5 -291.5,3416.5 ; -491.5,5791.5 -291.5,5791.5 ; 2008.5,-1333.5 2008.5,-1133.5 ; 2008.5,7966.5 2008.5,8166.5 ; 4508.5,-1333.5 4508.5,-1133.5 ; 4508.5,7966.5 4508.5,8166.5 ; 6321,-1133.5 6321,-523.5 11303.5,-523.5 ; 7008.5,-1333.5 7008.5,-1133.5 ; 7008.5,7966.5 7008.5,8166.5 ; 9508.5,-1333.5 9508.5,-1133.5 ; 9508.5,7966.5 9508.5,8166.5 ; 11303.5,-1133.5 11303.5,-523.5 ; 11303.5,-823.5 14303.5,-823.5 ; 11303.5,-223.5 14303.5,-223.5 ; 11304.5,370.5 14304.5,370.5 ; 12008.5,-1333.5 12008.5,-1133.5 ; 12008.5,7966.5 12008.5,8166.5 ; 12808.5,-1123.5 12808.5,-523.5 ; 14303.5,-523.5 11303.5,-523.5 ; 14303.5,76.5 11303.5,76.5 ; 14308.5,66.5 14308.5,-1133.5 ; 14308.5,871 11304.5,871 11303.5,871 11303.5,370.5 11303.5,76.5 ; 14308.5,1041.5 14508.5,1041.5 ; 14308.5,3416.5 14508.5,3416.5 ; 14308.5,5791.5 14508.5,5791.5 ; 11303.5,-523.5 11303.5,76.5 ; 14308.5,-1133.5 14308.5,7966.5 -291.5,7966.5 -291.5,-1133.5 14308.5,-1133.5 ; -491.5,-1333.5 -491.5,8166.5 14508.5,8166.5 14508.5,-1333.5 -491.5,-1333.5
  text "1" at 739.84,8036.5 h70
  text "2" at 3235.5,8036.5 h70
  text "3" at 5724.84,8036.5 h70
  text "4" at 8194.51,8036.5 h70
  text "5" at 10693.5,8036.5 h70
  text "6" at 13235.5,8036.5 h70
  text "A" at -416.5,6893.5 h70
  text "A" at 14383.5,6893.5 h70
  text "B" at -416.5,4513.5 h70
  text "B" at 14383.5,4513.5 h70
  text "C" at -416.5,2138.5 h70
  text "C" at 14383.5,2138.5 h70
  text "PROJECT TITLE:" at 11343.5,277.5 h45
  text ".PRJ_Title" at 11393.5,144.17 h70
  text "DESIGNED FOR:" at 11343.5,-23.5 h45
  text ".PRJ_Customer" at 11386.5,-182.16 h70
  text "D" at -416.5,-231.5 h70
  text "D" at 14383.5,-231.5 h70
  text "FILE NAME:" at 11343.5,-323.5 h45
  text ".PCB_File_Name_No_Path" at 11393.5,-443.5 h70
  text "Texas Instruments (TI) and/or its licensors do not warrant the accuracy or completeness of this specification" at 6374,-605.34 h45
  text "ENGINEER:" at 11343.5,-613.5 h45
  text "LAYOUT BY:" at 12848.5,-613.5 h45
  text "or any information contained therein. TI and/or its licensors do not warrant that this design will meet" at 6329.01,-718 h45
  text ".PRJ_Engineer" at 11393.5,-768.49 h70
  text ".Layout Engineer" at 12899,-768.49 h70
  text "the specifications, will be suitable for your application or fit for any particular purpose, or will operate in" at 6329.01,-830.67 h45
  text "ALTIUM DESIGNER VERSION:" at 12848.5,-923.5 h45
  text "an implementation. TI and/or its licensors do not warrant that the design is production worthy. You should" at 6329.01,-943.33 h45
  text "completely validate and test your design implementation to confirm the system functionality for your application." at 6374,-1056 h45
  text ".print_Scale" at 11393.5,-1056.83 h70
  text ".Application_BuildNumber" at 12899,-1056.83 h70
  text "1" at 739.84,-1263.5 h70
  text "2" at 3235.5,-1263.5 h70
  text "3" at 5724.84,-1263.5 h70
  text "4" at 8231.51,-1263.5 h70
  text "5" at 10730.5,-1263.5 h70
  text "6" at 13235.5,-1263.5 h70
M10 Fab Notes:
  drawing of 215 lines, arcs and shapes, not listed
  text "IMPEDANCE SPECIFICATIONS" at 175.78,7685.01 h120
  text "IMPEDANCE" at 742.32,7421.43 h100
  text "IMPEDANCE" at 1645.49,7421.43 h100
  text "(90 Ohms)" at 2419.99,7421.44 h100
  text "IMPEDANCE" at 3351.74,7421.43 h100
  text "(100 Ohms)" at 4145.74,7421.44 h100
  text "REFERENCE" at 5375.5,7421.43 h100
  text "LAYERS" at 123.37,7336.8 h100
  text "(50 Ohms)" at 719.78,7304.4 h100
  text "WIDTH" at 881.54,7163.45 h100
  text "WIDTH" at 1758.85,7163.45 h100
  text "SPACE" at 2566.39,7163.45 h100
  text "WIDTH" at 3465.09,7163.45 h100
  text "SPACE" at 4207.3,7163.45 h100
  text "LAYER" at 5561.32,7163.45 h100
  text "TOP" at 123.37,6957.83 h80
  text "5.3 MIL" at 742.32,6937.83 h100
  text "4.2 MIL" at 1758.85,6937.83 h100
  text "5 MIL" at 2535.94,6937.83 h100
  text "4 MIL" at 3465.09,6937.83 h100
  text "7.7 MIL" at 4158.2,6937.83 h100
  text "L2" at 5828.41,6937.83 h100
  text "SIG1" at 123.37,6627.02 h80
  text "4 MIL" at 742.32,6607.03 h100
  text "4  MIL" at 1758.85,6607.03 h100
  text "6 MIL" at 2535.94,6607.03 h100
  text "3.5 MIL" at 3465.09,6607.03 h100
  text "8.1 MIL" at 4158.2,6607.03 h100
  text "L2" at 5828.41,6607.03 h100
  text "DESIGN INFORMATION" at 12382.02,6356.17 h60
  text "BOTTOM" at 123.37,6318.26 h80
  text "5.3 MIL" at 742.32,6318.26 h100
  text "4.2 MIL" at 1758.85,6318.26 h100
  text "5 MIL" at 2535.94,6318.26 h100
  text "4 MIL" at 3465.09,6318.26 h100
  text "7.7 MIL" at 4158.2,6318.26 h100
  text "L5" at 5828.41,6318.26 h100
  text "MIN. TRACK WIDTH:" at 11737.46,6224.05 h60
  text "3.4" at 12833.7,6224.05 h60
  text "MIL" at 13024.46,6224.05 h60
  text "MIN. CLEARANCE:" at 11737.46,6099.92 h60
  text "3.2" at 12833.7,6099.92 h60
  text "MIL" at 13024.46,6099.92 h60
  text "MIN. VIA PAD SIZE:" at 11737.46,5975.8 h60
  text "18" at 12803.71,5975.8 h60
  text "MIL" at 12988.46,5975.8 h60
  text "0.05mm (2MIL)" at 12432.46,5845.9 h60
  text "MINIMUM ANNULAR RING" at 11408.23,5837.67 h60
  text "EXTERNAL" at 13140.46,5837.67 h60
  text "PER" at 11608.23,5727.55 h60
  text "IPC-D-275 CLASS 2 LEVEL C" at 11828.23,5727.54 h60
  text "MIL, HOLES" at 13316.46,5627.07 h60
  text "+/-" at 12924,5618.48 h60
  text "+/-" at 13778,5618.48 h60
  text "REGISTRATION TOLERANCES:" at 11408.23,5617.42 h60
  text "METAL" at 12608,5617.42 h60
  text "5" at 13184.2,5617.42 h60
  text "3" at 14017.2,5617.42 h60
  text "MIL" at 14133.46,5617.42 h60
  text "HOLE SIZE TOLERANCE (UNLESS OTHERWISE SPECIFIED):" at 11408.23,5519.1 h60
  text "+/-" at 13778,5516.23 h60
  text "3" at 14017.2,5515.17 h60
  text "MIL" at 14133.46,5515.17 h60
  text "MATERIAL:" at 11333.46,5377.52 h60
  text "FR-4 High Tg" at 12319.9,5249 h60
  text "X" at 12175.46,5241.01 h60
  text "FR-408" at 11754.46,5236.49 h60
  text "OTHER" at 13242.46,5236.49 h60
  text "62 MIL (1.6mm) +/-10%" at 12074.56,5093.46 h60
  text "X" at 11954.46,5091.01 h60
  text "THICKNESS:" at 11408.23,5085.24 h60
  text "OTHER" at 13359.46,5085.24 h60
  text "TOLERANCE:" at 11408.23,4946.92 h60
  text "X" at 12256.46,4946.92 h60
  text "ANSI IPC-6012 TYPE 3 CLASS 2" at 12434.48,4946.92 h60
  text "OTHER +/-" at 12434.46,4802.73 h60
  text "BOW & TWIST:" at 11408.23,4657.54 h60
  text "X" at 12256.46,4657.54 h60
  text "ANSI IPC-6012 TYPE 3 CLASS 2" at 12434.48,4657.54 h60
  text "OTHER +/-" at 12434.46,4510.85 h60
  text "DRILLING:" at 11333.46,4380.23 h60
  text "NC_DRILL FILES" at 13094.46,4275.04 h60
  text "REFERENCE:" at 11408.23,4271.1 h60
  text "X" at 12065.46,4271.01 h60
  text "AS SHOWN" at 12243.46,4271.1 h60
  text "X" at 12966.46,4271.1 h60
  text "OTHER" at 13392.46,4128.85 h60
  text "PTH COPPER THICKNESS:" at 11407.91,4125.32 h60
  text "X" at 12547.14,4125.32 h60
  text "20-30 um" at 12675.14,4125.32 h60
  text "BOARD FINISH:" at 11333.46,3977.73 h60
  text "SILKSCREEN:" at 11488.68,3867.6 h60
  text "X" at 12446.46,3867.6 h60
  text "TOP" at 12563.46,3867.6 h60
  text "X" at 12956.46,3867.6 h60
  text "BOTTOM" at 13074.46,3867.6 h60
  text "SILKSCREEN COLOR:" at 11488.68,3712.41 h60
  text "X" at 12445.46,3712.41 h60
  text "WHITE" at 12563.46,3712.41 h60
  text "OTHER" at 13074.46,3712.41 h60
  text "GREEN" at 12694.46,3568.96 h60
  text "X" at 13168.46,3568.96 h60
  text "OTHER" at 13312.46,3568.96 h60
  text "RED" at 13671.46,3568.96 h60
  text "SOLDER RESIST COLOR:" at 11488.68,3562.1 h60
  text "X" at 12576.46,3414.71 h60
  text "MATTE" at 12694.46,3414.71 h60
  text "SEMI-GLOSS" at 13312,3414.07 h60
  text "IMMERSION GOLD (ENIG)" at 12394.46,3241.94 h60
  text "ENEPIG" at 13732,3234.72 h60
  text "SURFACE FINISH:" at 11333.46,3233.72 h60
  text "X" at 12216.46,3233.72 h60
  text "IMM. TIN/SILVER OR EQUIV" at 11663,3096.4 h60
  text "OTHER" at 13094.46,3092.47 h60
  text "ARRAY/PANEL:" at 11333.46,2937.09 h60
  text "CUT AND TRIM PER M1 BOARD OUTLINE" at 12394.46,2928.87 h60
  text "N.C. ROUTE" at 12394.46,2792.9 h60
  text "X" at 13082.46,2792.9 h60
  text "V. SCORE" at 13260.46,2792.9 h60
  text "CERTIFICATION:" at 11333.46,2663.77 h60
  text "MATERIALS AND WORKMANSHIP FOR ALL PCBS" at 12058.46,2663.77 h60
  text "TO MEET OR EXCEED THE REQUIREMENTS OF:" at 12058.46,2569.71 h60
  text "X" at 11695.97,2441.08 h60
  text "ANSI IPC-A-600F CLASS ->" at 11823.96,2441.08 h60
  text "X" at 13471.97,2441.08 h60
  text "2" at 13581.96,2441.08 h60
  text "1" at 13266.96,2439.58 h60
  text "3" at 13935.96,2439.58 h60
  text "X" at 12507.97,2293.39 h60
  text "RoHS" at 12635.96,2293.39 h60
  text "OTHER" at 13280.36,2293.39 h60
  text "PER ORDER" at 13677.42,2293.39 h60
  text "ALL BOARDS MUST MEET OR EXCEED UL94-V0 REQUIREMENTS." at 11361,2139.57 h60
  text "PCB MUST BEAR THE UL94V-0 UL REGISTERED MATERIAL ID NUMBER" at 11361,2023.5 h60
  text "ADDITIONAL REQUIREMENTS:" at 11333.46,1854.08 h60
  text "MICROSECTION:" at 11408.23,1746.95 h60
  text "YES" at 12313.96,1746.95 h60
  text "REQUIRED" at 13175.46,1602.62 h60
  text "BARE BOARD ELEC. TEST:" at 11408.23,1599.76 h60
  text "NONE" at 12713.96,1599.76 h60
  text "X" at 13057.46,1599.76 h60
  text "PER ORDER" at 13767.46,1599.76 h60
  text "XX MIL VIAS REQUIRE NON-CONDUCTIVE FILL AND PLANARIZE" at 11576.38,1394.82 h59
  text "XX MIL VIAS REQUIRE CONDUCTIVE FILL AND PLANARIZE" at 11584.38,1290.84 h60
  text "OUTER XX MIL TRACES REQUIRE 50 OHM SINGLE-ENDED IMPEDANCE" at 11583.39,1127.46 h58
  text "LAYER 2 & 3 (INNER LAYERS) XX MIL WIDE, XX MIL SPACE / TRACES REQUIRE 100 OHM DIFFERENTIAL IMPEDANCE" at 11575.39,891.74 h60
  text ".Layer_Name" at 585,-896 h60
M11 Gerber Information:
  lines w10: -292,-930.17 6308,-930.17 ; -292,-726.83 6310,-726.83 ; -292,-523.5 -292,-1133.5 3713,-1133.5 6310,-1133.5 6310,-523.5 -291.5,-523.5 -291.5,-1133.5 1284,-1133.5 ; 2173,-1133.5 2173,-523.5 ; 3440,-726.83 3440,-523.5 ; 4280,-726.83 4280,-523.5 ; 4902,-1140 4902,-937.17
  text "ALL ARTWORK VIEWED FROM TOP SIDE" at -228.5,-655.67 h60
  text "BOARD #:" at 2248,-655.67 h60
  text ".PRJ_Number" at 2793.5,-655.67 h60
  text "REV:" at 3638,-655.67 h60
  text ".PCB_Rev" at 3929.5,-655.67 h60
  text "SVN REV:" at 4476,-655.67 h60
  text ".VersionControl_RevNumber" at 4982,-655.67 h60
  text "LAYER NAME =" at -228.5,-858.49 h60
  text "TID #:" at 2248,-859 h60
  text ".TID" at 2793.5,-859 h60
  text "PLOT NAME =" at -228.5,-1064.34 h60
  text ".plot_File_Name" at 577,-1064.34 h60
  text "GENERATED    :" at 2250,-1064.34 h60
  text ".Print_Date" at 3119.5,-1064.34 h60
  text ".Print_Time" at 3848.5,-1064.34 h60
  text "TEXAS INSTRUMENTS" at 5113,-1064.34 h60
M12 Stackup:
  lines w15: 8088.72,2916.52 8423.01,2916.52 9069.52,2916.52 10274.28,2916.52 10751.5,2916.52 11193.16,2916.52 ; 8088.72,3076.26 8423.01,3076.26 9069.52,3076.26 10274.28,3076.26 10751.5,3076.26 11193.16,3076.26 ; 8088.72,3236 8423.01,3236 9069.52,3236 10274.28,3236 10751.5,3236 11193.16,3236 ; 8088.72,3395.74 8423.01,3395.74 9069.52,3395.74 10274.28,3395.74 10751.5,3395.74 11193.16,3395.74 ; 8088.72,3555.48 8423.01,3555.48 9069.52,3555.48 10274.28,3555.48 10751.5,3555.48 11193.16,3555.48 ; 8088.72,3715.22 8423.01,3715.22 9069.52,3715.22 10274.28,3715.22 10751.5,3715.22 11193.16,3715.22 ; 8088.72,3874.96 8423.01,3874.96 9069.52,3874.96 10274.28,3874.96 10751.5,3874.96 11193.16,3874.96 ; 8088.72,4034.69 8423.01,4034.69 9069.52,4034.69 10274.28,4034.69 10751.5,4034.69 11193.16,4034.69 ; 8088.72,4194.43 8423.01,4194.43 9069.52,4194.43 10274.28,4194.43 10751.5,4194.43 11193.16,4194.43 ; 8088.72,4354.17 8423.01,4354.17 9069.52,4354.17 10274.28,4354.17 10751.5,4354.17 11193.16,4354.17 ; 8088.72,4513.91 8423.01,4513.91 9069.52,4513.91 10274.28,4513.91 10751.5,4513.91 11193.16,4513.91 ; 8088.72,4673.65 8423.01,4673.65 9069.52,4673.65 10274.28,4673.65 10751.5,4673.65 11193.16,4673.65 ; 8088.72,4833.39 8423.01,4833.39 9069.52,4833.39 10274.28,4833.39 10751.5,4833.39 11193.16,4833.39 ; 8088.72,4993.13 8423.01,4993.13 9069.52,4993.13 10274.28,4993.13 10751.5,4993.13 11193.16,4993.13 ; 8088.72,5152.87 8423.01,5152.87 9069.52,5152.87 10274.28,5152.87 10751.5,5152.87 11193.16,5152.87 ; 8088.72,5312.61 8423.01,5312.61 9069.52,5312.61 10274.28,5312.61 10751.5,5312.61 11193.16,5312.61 ; 8088.72,5472.34 8423.01,5472.34 9069.52,5472.34 10274.28,5472.34 10751.5,5472.34 11193.16,5472.34 ; 8088.72,5632.08 8423.01,5632.08 9069.52,5632.08 10274.28,5632.08 10751.5,5632.08 11193.16,5632.08 ; 8088.72,5791.82 11193.16,5791.82 ; 8423.01,5951.56 8423.01,2756.78 ; 9069.52,5951.56 9069.52,2756.78 ; 10274.28,5951.56 10274.28,2756.78 ; 10751.5,5951.56 10751.5,2756.78 ; 8423.01,2756.78 8088.72,2756.78 8088.72,5951.56 11193.16,5951.56 11193.16,2756.78 10751.5,2756.78 ; 8423.01,2756.78 9069.52,2756.78 ; 9069.52,2756.78 10274.28,2756.78 ; 10274.28,2756.78 10751.5,2756.78
  text "Layer" at 8168.59,5831.76 h79.87
  text "Name" at 8502.88,5831.76 h79.87
  text "Material" at 9149.39,5831.76 h79.87
  text "Thickness" at 10354.15,5831.76 h79.87
  text "Constant" at 10831.37,5831.76 h79.87
  text "Top Overlay" at 8502.88,5672.02 h79.87
  text "Top Solder" at 8502.88,5512.28 h79.87
  text "Taiyo PSR 4000 HFX DI-GREEN" at 9149.39,5512.28 h79.87
  text "1.00mil" at 10354.15,5512.28 h79.87
  text "3.5" at 10831.37,5512.28 h79.87
  text "1" at 8168.59,5352.54 h79.87
  text "Top Layer" at 8502.88,5352.54 h79.87
  text "Copper Foil 18 microns" at 9149.39,5352.54 h79.87
  text "2.09mil" at 10354.08,5352.54 h79.87
  text "Dielectric 1" at 8502.88,5192.8 h79.87
  text "Iteq IT180A Prepreg 2113 RC58" at 9149.39,5192.8 h79.87
  text "3.51mil" at 10354.15,5192.8 h79.87
  text "4.13" at 10831.37,5192.8 h79.87
  text "2" at 8168.51,5033.06 h79.87
  text "GND 1" at 8502.88,5033.06 h79.87
  text "1.26mil" at 10354.15,5033.06 h79.87
  text "Dielectric 3" at 8502.88,4873.32 h79.87
  text "Iteq IT180A 4 mil core 1/1" at 9149.39,4873.32 h79.87
  text "4.00mil" at 10354.15,4873.32 h79.87
  text "4.4" at 10831.37,4873.32 h79.87
  text "3" at 8168.59,4713.58 h79.87
  text "SIG 1" at 8502.88,4713.58 h79.87
  text "1.26mil" at 10354.15,4713.58 h79.87
  text "Dielectric 5" at 8502.88,4553.85 h79.87
  text "Composite dielectric" at 9149.39,4553.85 h79.87
  text "1.75mil" at 10354.15,4553.85 h79.87
  text "3.79" at 10831.37,4553.85 h79.87
  text "Dielectric 6" at 8502.88,4394.11 h79.87
  text "Composite dielectric" at 9149.39,4394.11 h79.87
  text "2.66mil" at 10354.08,4394.11 h79.87
  text "3.86" at 10831.37,4394.11 h79.87
  text "Dielectric1" at 8502.88,4234.37 h79.87
  text "Iteq IT180A 28 mil core H/H" at 9149.39,4234.37 h79.87
  text "28.00mil" at 10354.08,4234.37 h79.87
  text "4.53" at 10831.37,4234.37 h79.87
  text "Dielectric 7" at 8502.88,4074.63 h79.87
  text "Composite dielectric" at 9149.39,4074.63 h79.87
  text "2.66mil" at 10354.08,4074.63 h79.87
  text "3.86" at 10831.37,4074.63 h79.87
  text "Dielectric 8" at 8502.88,3914.89 h79.87
  text "Composite dielectric" at 9149.39,3914.89 h79.87
  text "1.75mil" at 10354.15,3914.89 h79.87
  text "3.79" at 10831.37,3914.89 h79.87
  text "4" at 8168.59,3755.15 h79.87
  text "SIG 2" at 8502.88,3755.15 h79.87
  text "1.26mil" at 10354.15,3755.15 h79.87
  text "Dielectric 4" at 8502.88,3595.41 h79.87
  text "Iteq IT180A 4 mil core 1/1" at 9149.39,3595.41 h79.87
  text "4.00mil" at 10354.15,3595.41 h79.87
  text "4.4" at 10831.37,3595.41 h79.87
  text "5" at 8168.59,3435.67 h79.87
  text "GND 2" at 8502.88,3435.67 h79.87
  text "1.26mil" at 10354.15,3435.67 h79.87
  text "Dielectric 2" at 8502.88,3275.93 h79.87
  text "Iteq IT180A Prepreg 2113 RC58" at 9149.39,3275.93 h79.87
  text "3.51mil" at 10354.15,3275.93 h79.87
  text "4.13" at 10831.37,3275.93 h79.87
  text "6" at 8168.59,3116.2 h79.87
  text "Bottom Layer" at 8502.88,3116.2 h79.87
  text "Copper Foil 18 microns" at 9149.39,3116.2 h79.87
  text "2.09mil" at 10354.08,3116.2 h79.87
  text "Bottom Solder" at 8502.88,2956.46 h79.87
  text "Taiyo PSR 4000 HFX DI-GREEN" at 9149.39,2956.46 h79.87
  text "1.00mil" at 10354.15,2956.46 h79.87
  text "3.5" at 10831.37,2956.46 h79.87
  text "Bottom Overlay" at 8502.88,2796.72 h79.87
  text ".Layer_Name" at 577,-858.49 h60
M13 Component Bodies Top:
  text ".Layer_Name" at 577,-858.49 h60
M14 Component Bodies Bottom:
  text ".Layer_Name" at 577,-858.49 h60
M15 Courtyards Top:
  text ".Layer_Name" at 577,-858.49 h60
M16 Courtyards Bottom:
  text ".Layer_Name" at 577,-858.49 h60
Drill Drawing:
  drawing of 183 lines, arcs and shapes, not listed
  text "Symbol" at 6740.17,7587.3 h41.17
  text "Count" at 7043.15,7587.3 h41.17
  text "Hole Size" at 7423.31,7587.3 h41.17
  text "Plated" at 8089.29,7587.3 h41.17
  text "Hole Type" at 8392.27,7587.3 h41.17
  text "Drill Layer Pair" at 8825.59,7587.3 h41.17
  text "Hole Tolerance (+)" at 9691.65,7587.3 h41.17
  text "Hole Tolerance (-)" at 10467.96,7587.3 h41.17
  text "128" at 7043.15,7501.53 h34.31
  text "7.87mil (0.200mm)" at 7423.31,7501.53 h34.31
  text "PTH" at 8089.29,7501.53 h34.31
  text "Round" at 8392.27,7501.53 h34.31
  text "Top Layer - Bottom Layer" at 8825.59,7501.53 h34.31
  text "3.00mil (0.076mm)" at 9691.65,7501.53 h34.31
  text "3.00mil (0.076mm)" at 10467.96,7501.53 h34.31
  text "1595" at 7043.15,7415.75 h34.31
  text "8.00mil (0.203mm)" at 7423.31,7415.75 h34.31
  text "PTH" at 8089.29,7415.75 h34.31
  text "Round" at 8392.27,7415.75 h34.31
  text "Top Layer - Bottom Layer" at 8825.59,7415.75 h34.31
  text "3.00mil (0.076mm)" at 9691.65,7415.75 h34.31
  text "3.00mil (0.076mm)" at 10467.96,7415.75 h34.31
  text "2" at 7043.15,7329.98 h34.31
  text "23.62mil (0.600mm)" at 7423.31,7329.98 h34.31
  text "PTH" at 8089.29,7329.98 h34.31
  text "Slot" at 8392.27,7329.98 h34.31
  text "Top Layer - Bottom Layer" at 8825.59,7329.98 h34.31
  text "3.00mil (0.076mm)" at 9691.65,7329.98 h34.31
  text "3.00mil (0.076mm)" at 10467.96,7329.98 h34.31
  text "48" at 7043.15,7244.2 h34.31
  text "32.00mil (0.813mm)" at 7423.31,7244.2 h34.31
  text "NPTH" at 8089.29,7244.2 h34.31
  text "Round" at 8392.27,7244.2 h34.31
  text "Top Layer - Bottom Layer" at 8825.59,7244.2 h34.31
  text "3.00mil (0.076mm)" at 9691.65,7244.2 h34.31
  text "3.00mil (0.076mm)" at 10467.96,7244.2 h34.31
  text "20" at 7043.15,7158.43 h34.31
  text "35.43mil (0.900mm)" at 7423.31,7158.43 h34.31
  text "PTH" at 8089.29,7158.43 h34.31
  text "Round" at 8392.27,7158.43 h34.31
  text "Top Layer - Bottom Layer" at 8825.59,7158.43 h34.31
  text "3.00mil (0.076mm)" at 9691.65,7158.43 h34.31
  text "3.00mil (0.076mm)" at 10467.96,7158.43 h34.31
  text "10" at 7043.15,7072.65 h34.31
  text "39.37mil (1.000mm)" at 7423.31,7072.65 h34.31
  text "PTH" at 8089.29,7072.65 h34.31
  text "Round" at 8392.27,7072.65 h34.31
  text "Top Layer - Bottom Layer" at 8825.59,7072.65 h34.31
  text "3.00mil (0.076mm)" at 9691.65,7072.65 h34.31
  text "3.00mil (0.076mm)" at 10467.96,7072.65 h34.31
  text "34" at 7043.15,6986.87 h34.31
  text "40.00mil (1.016mm)" at 7423.31,6986.87 h34.31
  text "PTH" at 8089.29,6986.87 h34.31
  text "Round" at 8392.27,6986.87 h34.31
  text "Top Layer - Bottom Layer" at 8825.59,6986.87 h34.31
  text "3.00mil (0.076mm)" at 9691.65,6986.87 h34.31
  text "3.00mil (0.076mm)" at 10467.96,6986.87 h34.31
  text "88" at 7043.15,6901.1 h34.31
  text "40.16mil (1.020mm)" at 7423.31,6901.1 h34.31
  text "PTH" at 8089.29,6901.1 h34.31
  text "Round" at 8392.27,6901.1 h34.31
  text "Top Layer - Bottom Layer" at 8825.59,6901.1 h34.31
  text "3.00mil (0.076mm)" at 9691.65,6901.1 h34.31
  text "3.00mil (0.076mm)" at 10467.96,6901.1 h34.31
  text "3" at 7043.15,6815.32 h34.31
  text "47.24mil (1.200mm)" at 7423.31,6815.32 h34.31
  text "PTH" at 8089.29,6815.32 h34.31
  text "Round" at 8392.27,6815.32 h34.31
  text "Top Layer - Bottom Layer" at 8825.59,6815.32 h34.31
  text "3.00mil (0.076mm)" at 9691.65,6815.32 h34.31
  text "3.00mil (0.076mm)" at 10467.96,6815.32 h34.31
  text "2" at 7043.15,6729.55 h34.31
  text "62.99mil (1.600mm)" at 7423.31,6729.55 h34.31
  text "PTH" at 8089.29,6729.55 h34.31
  text "Slot" at 8392.27,6729.55 h34.31
  text "Top Layer - Bottom Layer" at 8825.59,6729.55 h34.31
  text "3.00mil (0.076mm)" at 9691.65,6729.55 h34.31
  text "3.00mil (0.076mm)" at 10467.96,6729.55 h34.31
  text "4" at 7043.15,6643.77 h34.31
  text "66.93mil (1.700mm)" at 7423.31,6643.77 h34.31
  text "PTH" at 8089.29,6643.77 h34.31
  text "Round" at 8392.27,6643.77 h34.31
  text "Top Layer - Bottom Layer" at 8825.59,6643.77 h34.31
  text "3.00mil (0.076mm)" at 9691.65,6643.77 h34.31
  text "3.00mil (0.076mm)" at 10467.96,6643.77 h34.31
  text "2" at 7043.15,6558 h34.31
  text "82.68mil (2.100mm)" at 7423.31,6558 h34.31
  text "PTH" at 8089.29,6558 h34.31
  text "Slot" at 8392.27,6558 h34.31
  text "Top Layer - Bottom Layer" at 8825.59,6558 h34.31
  text "3.00mil (0.076mm)" at 9691.65,6558 h34.31
  text "3.00mil (0.076mm)" at 10467.96,6558 h34.31
  text "10" at 7043.15,6472.22 h34.31
  text "126.00mil (3.200mm)" at 7423.31,6472.22 h34.31
  text "NPTH" at 8089.29,6472.22 h34.31
  text "Round" at 8392.27,6472.22 h34.31
  text "Top Layer - Bottom Layer" at 8825.59,6472.22 h34.31
  text "3.00mil (0.076mm)" at 9691.65,6472.22 h34.31
  text "3.00mil (0.076mm)" at 10467.96,6472.22 h34.31
  text "4" at 7043.15,6386.44 h34.31
  text "127.95mil (3.250mm)" at 7423.31,6386.44 h34.31
  text "NPTH" at 8089.29,6386.44 h34.31
  text "Round" at 8392.27,6386.44 h34.31
  text "Top Layer - Bottom Layer" at 8825.59,6386.44 h34.31
  text "3.00mil (0.076mm)" at 9691.65,6386.44 h34.31
  text "3.00mil (0.076mm)" at 10467.96,6386.44 h34.31
  text "1950 Total" at 7043.15,6300.67 h34.31
  text "Slot definitions :" at 6740.17,6209.2 h34.31
  text "Routed Path Length" at 7342.69,6209.2 h34.31
  text "= Calculated from tool start centre position to tool end centre position." at 7985.23,6209.2 h34.31
  text "Hole Length" at 7342.69,6143.47 h34.31
  text "= Routed Path Length + Tool Size = Slot length as defined in the PCB layout" at 7750.85,6143.47 h34.31
  text ".Layer_Name" at 577,-858.49 h60
M17 Embedded Cavity:
  text ".Layer_Name" at 577,-858.49 h60
M18 Embedded Assembly:
  text ".Layer_Name" at 577,-858.49 h60
M19 Embedded Keepout:
  text ".Layer_Name" at 577,-858.49 h60
DXF_PROC109E2_TASY:
  drawing of 6230 lines, arcs and shapes, not listed
DXF_PROC109E2_BASY:
  drawing of 6782 lines, arcs and shapes, not listed
  text "WHEN ACTUATOR IS OPENED" at -622.58,-301.75 h30 r270
  text "WHEN ACTUATOR IS OPENED" at -622.58,-301.75 h30 r270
